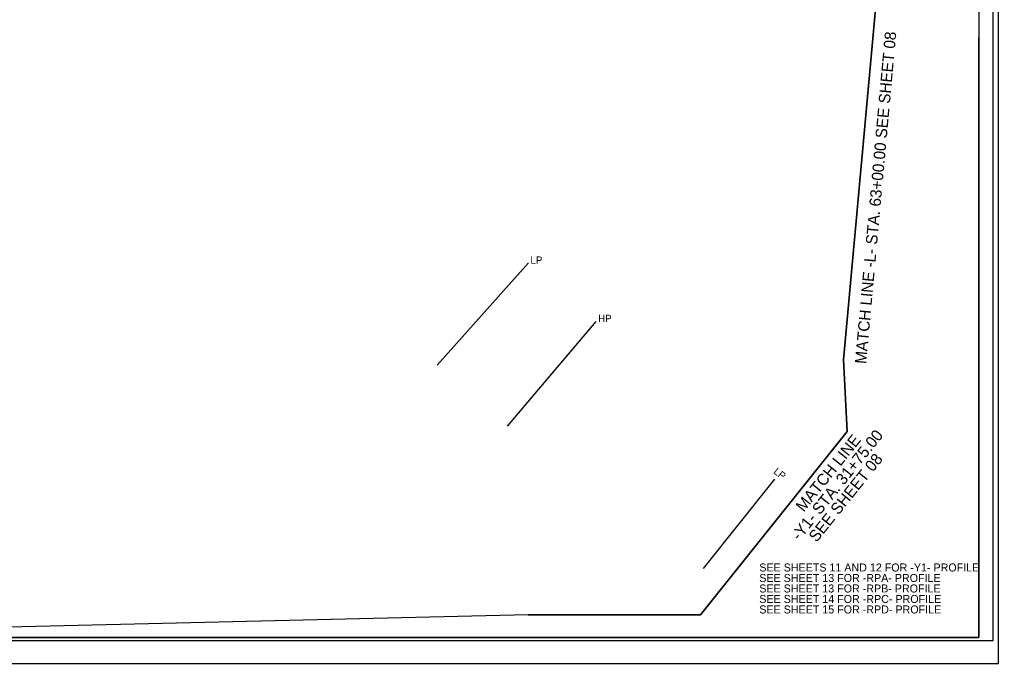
# Model space of a CAD drawing. Extents: x 1639431 to 1642602, y 841916 to 843940.
# Drawn here: x 1641031 to 1641888, y 841916 to 842479 of the extents above; entities that cross this region are included whole.
import ezdxf

# ---------------------------------------------------------------- set-up
doc = ezdxf.new("R2010")
doc.units = 0
for name, color, linetype in [('Matchline', 7, 'Continuous'), ('Matchline Text', 7, 'Continuous'), ('Old_Level_1', 7, 'Continuous'), ('Prop Dimension', 7, 'Continuous'), ('Sheet Clip Boundary CELL', 7, 'Continuous'), ('Sheet Cutting Line CELL', 7, 'Continuous'), ('Sheet Plan CELL', 7, 'Continuous'), ('Sheet Plot Border Inside CELL', 7, 'Continuous'), ('Sheet Plot Border Outside CELL', 7, 'Continuous')]:
    doc.layers.add(name, color=color, linetype=linetype)

msp = doc.modelspace()

# ---------------------------------------------------------------- linework, layer by layer
at = {"layer": 'Matchline'}
msp.add_line((1641476.31, 841958.82), (1641627.07, 841958.82), dxfattribs=at)
msp.add_lwpolyline([(1641627.07, 841958.82), (1641755.49, 842119.21), (1641752.38, 842181.83), (1641796.56, 842667.29)], dxfattribs=at)
at = {"layer": 'Old_Level_1'}
for p, q in [((1641396.6, 842177.18), (1641476.53, 842266.68)), ((1641458.17, 842123.65), (1641535.69, 842215.25)), ((1641629.83, 841999.24), (1641692.16, 842077.45))]:
    msp.add_line(p, q, dxfattribs=at)
at = {"layer": 'Sheet Clip Boundary CELL'}
for points in [[(1641443.85, 842919.31), (1641444.34, 842714.97), (1641747.5, 842714.54), (1641796.56, 842667.29), (1641752.38, 842181.83), (1641755.49, 842119.21), (1641627.07, 841958.82)], [(1641627.07, 841958.82), (1641476.31, 841958.82), (1640885.35, 841944.88), (1640879.04, 842022.1), (1640881.13, 842043.37), (1640760.23, 842041.75), (1640760.69, 842110.15), (1640760.04, 842113.92), (1640759.14, 842119.04), (1640760.54, 842128.84), (1640539.36, 842129.01), (1640414.85, 842129.76)]]:
    msp.add_lwpolyline(points, dxfattribs=at)
at = {"layer": 'Sheet Cutting Line CELL'}
msp.add_line((1640204.3, 841916.31), (1641887.8, 841916.31), dxfattribs=at)
at = {"layer": 'Sheet Plan CELL'}
for points in [[(1640370.79, 841938.82), (1640370.76, 842988.79), (1641670.75, 842988.83), (1641670.76, 842838.77), (1641870.8, 842838.76), (1641870.8, 841938.82)], [(1641870.83, 842988.82), (1640370.79, 842988.82), (1640370.79, 841938.82), (1641870.8, 841938.82)]]:
    msp.add_lwpolyline(points, close=True, dxfattribs=at)
at = {"layer": 'Sheet Plot Border Inside CELL'}
msp.add_lwpolyline([(1640217.3, 841936.31), (1641883.29, 841936.32), (1641883.3, 842991.31), (1640217.3, 842991.31)], close=True, dxfattribs=at)
at = {"layer": 'Sheet Plot Border Outside CELL'}
msp.add_lwpolyline([(1640204.3, 841916.31), (1641887.8, 841916.31), (1641887.8, 843011.31), (1640204.3, 843011.31)], close=True, dxfattribs=at)
msp.add_lwpolyline([(1640204.3, 841916.31), (1641887.8, 841916.31), (1641887.8, 843011.31), (1640204.3, 843011.31)], close=True, dxfattribs=at)

# ---------------------------------------------------------------- texts
at = {"layer": 'Matchline Text'}
for s, rotation, p in [('MATCH LINE -L- STA. 63+00.00 SEE SHEET 08', 84.80047, (1641772.11, 842177.86)), ('-Y1- STA. 31+75.00', 51.31933, (1641713.5, 842022.95)), ('MATCH LINE', 51.31933, (1641717.43, 842048.14)), ('SEE SHEET 08', 51.31933, (1641728.73, 842021.69))]:
    msp.add_text(s, height=10, rotation=rotation, dxfattribs=at).set_placement(p)
at = {"layer": 'Old_Level_1'}
for s, rotation, p in [('LP', 360, (1641478.32, 842265.76)), ('HP', 360, (1641537.56, 842214.79)), ('LP', 321.44605, (1641690.41, 842083.11))]:
    msp.add_text(s, height=6.375, rotation=rotation, dxfattribs=at).set_placement(p)
at = {"layer": 'Prop Dimension'}
for s, p in [('SEE SHEETS 11 AND 12 FOR -Y1- PROFILE', (1641678.57, 841996.68)), ('SEE SHEET 13 FOR -RPA- PROFILE', (1641678.57, 841987.51)), ('SEE SHEET 13 FOR -RPB- PROFILE', (1641678.57, 841978.33)), ('SEE SHEET 14 FOR -RPC- PROFILE', (1641678.57, 841969.15)), ('SEE SHEET 15 FOR -RPD- PROFILE', (1641678.57, 841959.98))]:
    msp.add_text(s, height=7, rotation=360, dxfattribs=at).set_placement(p)

doc.saveas('drawing.dxf')
